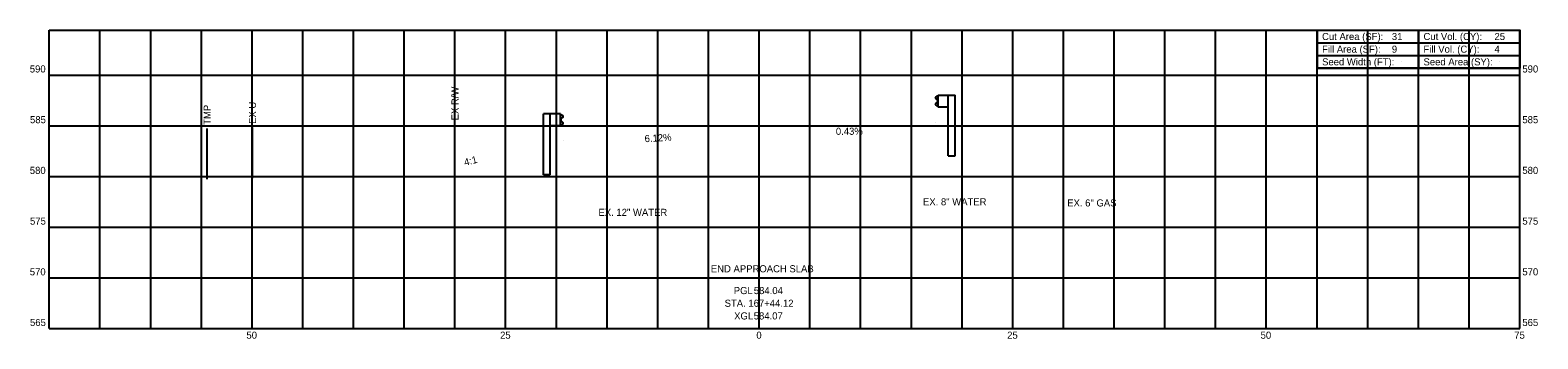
# Model space of a CAD drawing. Extents: x -72 to 77, y 564 to 594.
import ezdxf

# ---------------------------------------------------------------- set-up
doc = ezdxf.new("R2010")
doc.units = 0
for name, color, linetype in [('BD_X_Building', 7, 'Continuous'), ('BD_X_Canopy', 7, 'Continuous'), ('Default', 7, 'Continuous'), ('RD_X_Cells', 7, 'Continuous'), ('RD_X_Concrete_Pad', 7, 'Continuous'), ('RD_X_Fence', 7, 'Continuous'), ('SN_X_Public', 7, 'Continuous'), ('SV_X_Top_of_Bank', 7, 'Continuous'), ('UT_X_Cable_TV', 7, 'Continuous'), ('UT_X_Telecom', 7, 'Continuous')]:
    doc.layers.add(name, color=color, linetype=linetype)

msp = doc.modelspace()

# ---------------------------------------------------------------- linework, layer by layer
at = {"layer": 'BD_X_Canopy'}
msp.add_line((-30, 580.18), (-30, 585.18), dxfattribs=at)
at = {"layer": 'Default'}
msp.add_circle((75, 594.42), 0.000417, dxfattribs=at)
msp.add_circle((75, 594.42), 0.000417, dxfattribs=at)
msp.add_circle((75, 594.42), 0.000417, dxfattribs=at)
msp.add_circle((75, 594.42), 0.000417, dxfattribs=at)
msp.add_circle((75, 594.42), 0.000417, dxfattribs=at)
msp.add_circle((75, 594.42), 0.000417, dxfattribs=at)
msp.add_circle((75, 594.42), 0.000417, dxfattribs=at)
msp.add_circle((75, 594.42), 0.000417, dxfattribs=at)
msp.add_circle((75, 594.42), 0.000417, dxfattribs=at)
msp.add_circle((75, 594.42), 0.000417, dxfattribs=at)
msp.add_circle((75, 594.42), 0.000417, dxfattribs=at)
msp.add_circle((75, 594.42), 0.000417, dxfattribs=at)
at = {"layer": 'RD_X_Concrete_Pad'}
for p, q in [((-70, 594.42), (75, 594.42)), ((-70, 565), (-70, 594.42)), ((-65, 565), (-65, 594.42)), ((-60, 565), (-60, 594.42)), ((-55, 565), (-55, 594.42)), ((-50, 565), (-50, 594.42)), ((-45, 565), (-45, 594.42)), ((-40, 565), (-40, 594.42)), ((-35, 565), (-35, 594.42)), ((-30, 565), (-30, 594.42)), ((-25, 565), (-25, 594.42)), ((-20, 565), (-20, 594.42)), ((-15, 565), (-15, 594.42)), ((-10, 565), (-10, 594.42)), ((-5, 565), (-5, 594.42)), ((0, 565), (0, 594.42)), ((5, 565), (5, 594.42)), ((10, 565), (10, 594.42)), ((15, 565), (15, 594.42)), ((20, 565), (20, 594.42)), ((25, 565), (25, 594.42)), ((30, 565), (30, 594.42)), ((35, 565), (35, 594.42)), ((40, 565), (40, 594.42)), ((45, 565), (45, 594.42)), ((50, 565), (50, 594.42)), ((55, 565), (55, 594.42)), ((60, 565), (60, 594.42)), ((65, 565), (65, 594.42)), ((70, 565), (70, 594.42)), ((75, 565), (75, 594.42)), ((-70, 590), (75, 590)), ((-70, 585), (75, 585)), ((-70, 580), (75, 580)), ((-70, 575), (75, 575)), ((-70, 570), (75, 570)), ((-70, 565), (75, 565))]:
    msp.add_line(p, q, dxfattribs=at)
at = {"layer": 'RD_X_Fence'}
msp.add_lwpolyline([(55, 594.42), (75, 594.42), (75, 590.67), (55, 590.67)], close=True, dxfattribs=at)
at = {"layer": 'SN_X_Public'}
for p, q in [((55, 594.42), (75, 594.42)), ((55, 594.42), (55, 591.92)), ((55, 593.17), (75, 593.17)), ((65, 594.42), (65, 590.67)), ((75, 594.42), (75, 591.92)), ((55, 591.92), (75, 591.92)), ((63.3, 591.3), (63.3, 591.3)), ((72.95, 591.3), (72.95, 591.3))]:
    msp.add_line(p, q, dxfattribs=at)
msp.add_lwpolyline([(55, 591.92), (55, 590.67), (75, 590.67), (75, 591.92)], dxfattribs=at)
at = {"layer": 'SV_X_Top_of_Bank'}
for p, q in [((17.36, 587.76), (17.36, 587.76)), ((17.37, 587.76), (17.37, 587.76)), ((17.54, 587.93), (17.4, 587.83)), ((17.4, 587.82), (17.54, 587.92)), ((17.4, 587.83), (17.4, 587.83)), ((17.4, 587.82), (17.4, 587.82)), ((17.4, 587.69), (17.4, 587.69)), ((17.59, 587.55), (17.4, 587.69)), ((17.4, 587.68), (17.4, 587.68)), ((17.4, 587.68), (17.58, 587.55)), ((17.58, 587.33), (17.4, 587.19)), ((17.4, 587.18), (17.59, 587.32)), ((17.52, 587.92), (17.52, 587.92)), ((17.52, 587.91), (17.52, 587.91)), ((17.52, 587.6), (17.52, 587.6)), ((17.52, 587.6), (17.52, 587.6)), ((17.63, 587.95), (17.54, 587.93)), ((17.54, 587.92), (17.63, 587.94)), ((17.54, 587.93), (17.54, 587.93)), ((17.54, 587.92), (17.54, 587.92)), ((17.58, 587.55), (17.58, 587.55)), ((17.58, 587.33), (17.58, 587.33)), ((17.59, 587.55), (17.59, 587.55)), ((17.59, 587.32), (17.59, 587.32)), ((17.62, 587.48), (17.62, 587.48)), ((17.62, 587.48), (17.62, 587.39)), ((17.62, 587.41), (17.62, 587.47)), ((17.62, 587.39), (17.62, 587.39)), ((17.63, 587.95), (17.63, 587.95)), ((17.63, 587.94), (17.63, 587.95)), ((17.63, 587.94), (17.63, 587.94)), ((17.63, 587.48), (17.63, 587.48)), ((17.63, 587.39), (17.63, 587.48)), ((17.63, 587.41), (17.63, 587.47)), ((17.63, 587.39), (17.63, 587.39)), ((17.64, 588.02), (18.64, 588.02)), ((17.64, 586.85), (17.64, 588.02)), ((18.64, 588.02), (19.31, 588.02)), ((18.64, 582.02), (18.64, 588.02)), ((19.31, 582.02), (19.31, 588.02)), ((-20.6, 586.16), (-21.27, 586.16)), ((-21.27, 580.16), (-21.27, 586.16)), ((-19.6, 586.16), (-20.6, 586.16)), ((-20.6, 580.16), (-20.6, 586.16)), ((-19.6, 584.99), (-19.6, 586.16)), ((-19.59, 586.09), (-19.59, 586.09)), ((-19.59, 586.09), (-19.5, 586.08)), ((-19.59, 586.08), (-19.59, 586.09)), ((-19.59, 586.08), (-19.59, 586.08)), ((-19.5, 586.07), (-19.59, 586.08)), ((-19.55, 585.7), (-19.36, 585.83)), ((-19.36, 585.83), (-19.54, 585.69)), ((-19.5, 586.08), (-19.5, 586.08)), ((-19.5, 586.08), (-19.36, 585.97)), ((-19.5, 586.07), (-19.5, 586.07)), ((-19.36, 585.96), (-19.5, 586.07)), ((-19.48, 586.06), (-19.48, 586.06)), ((-19.48, 586.05), (-19.48, 586.05)), ((-19.48, 585.75), (-19.48, 585.75)), ((-19.48, 585.74), (-19.48, 585.74)), ((-19.36, 585.97), (-19.36, 585.97)), ((-19.36, 585.96), (-19.36, 585.96)), ((-19.36, 585.83), (-19.36, 585.83)), ((-19.36, 585.83), (-19.36, 585.83)), ((-19.33, 585.9), (-19.33, 585.9)), ((-19.32, 585.9), (-19.32, 585.9)), ((17.36, 587.12), (17.36, 587.12)), ((17.37, 587.12), (17.37, 587.12)), ((17.39, 587.05), (17.39, 587.05)), ((17.39, 587.05), (17.54, 586.94)), ((17.4, 587.19), (17.4, 587.19)), ((17.4, 587.18), (17.4, 587.18)), ((17.4, 587.06), (17.4, 587.06)), ((17.54, 586.95), (17.4, 587.06)), ((17.62, 586.93), (17.54, 586.95)), ((17.54, 586.94), (17.62, 586.92)), ((17.62, 586.93), (17.62, 586.93)), ((17.62, 586.92), (17.62, 586.93)), ((17.62, 586.92), (17.62, 586.92)), ((17.64, 586.85), (18.64, 586.85)), ((-19.6, 584.99), (-20.6, 584.99)), ((-19.59, 585.62), (-19.59, 585.62)), ((-19.59, 585.53), (-19.59, 585.62)), ((-19.59, 585.55), (-19.59, 585.61)), ((-19.59, 585.53), (-19.59, 585.53)), ((-19.58, 585.62), (-19.58, 585.62)), ((-19.58, 585.62), (-19.58, 585.53)), ((-19.58, 585.55), (-19.58, 585.61)), ((-19.58, 585.53), (-19.58, 585.53)), ((-19.58, 585.08), (-19.5, 585.09)), ((-19.58, 585.08), (-19.58, 585.08)), ((-19.58, 585.07), (-19.58, 585.08)), ((-19.5, 585.08), (-19.58, 585.07)), ((-19.58, 585.07), (-19.58, 585.07)), ((-19.55, 585.7), (-19.55, 585.7)), ((-19.55, 585.46), (-19.55, 585.46)), ((-19.36, 585.32), (-19.55, 585.46)), ((-19.54, 585.69), (-19.54, 585.69)), ((-19.54, 585.47), (-19.54, 585.47)), ((-19.54, 585.47), (-19.36, 585.33)), ((-19.5, 585.09), (-19.36, 585.2)), ((-19.35, 585.19), (-19.5, 585.08)), ((-19.36, 585.33), (-19.36, 585.33)), ((-19.36, 585.32), (-19.36, 585.32)), ((-19.36, 585.2), (-19.36, 585.2)), ((-19.35, 585.19), (-19.35, 585.19)), ((-19.33, 585.26), (-19.33, 585.26)), ((-19.32, 585.26), (-19.32, 585.26)), ((17.36, 585.35), (17.36, 585.35)), ((-19.32, 583.5), (-19.32, 583.5)), ((18.64, 582.02), (19.31, 582.02)), ((-20.6, 580.16), (-21.27, 580.16))]:
    msp.add_line(p, q, dxfattribs=at)
for points in [[(17.61, 587.46), (17.61, 587.41), (17.58, 587.41), (17.58, 587.46)], [(17.61, 587.5), (17.61, 587.38), (17.62, 587.38), (17.62, 587.5)], [(-19.57, 585.64), (-19.57, 585.52), (-19.58, 585.52), (-19.58, 585.64)], [(-19.57, 585.61), (-19.57, 585.55), (-19.54, 585.55), (-19.54, 585.61)]]:
    msp.add_lwpolyline(points, close=True, dxfattribs=at)
for centre, radius, start, end in [((17.45, 587.76), 0.0886, 126.7788, 233.682), ((17.45, 587.76), 0.0787, 126.7788, 233.682), ((17.54, 587.48), 0.0788, 359.9056, 53.682), ((17.54, 587.39), 0.0788, 306.1293, 359.9056), ((17.54, 587.48), 0.0886, 359.9056, 53.682), ((17.54, 587.39), 0.0886, 306.1293, 359.9056), ((-19.41, 585.9), 0.0886, 306.318, 53.2212), ((-19.41, 585.9), 0.0787, 306.318, 53.2212), ((17.45, 587.12), 0.0886, 126.1293, 233.0325), ((17.45, 587.12), 0.0787, 126.1293, 233.0325), ((-19.5, 585.62), 0.0886, 126.318, 180.0944), ((-19.5, 585.53), 0.0886, 180.0944, 233.8707), ((-19.5, 585.62), 0.0788, 126.318, 180.0944), ((-19.5, 585.53), 0.0788, 180.0944, 233.8707), ((-19.41, 585.26), 0.0886, 306.9675, 53.8707), ((-19.41, 585.26), 0.0787, 306.9675, 53.8707)]:
    msp.add_arc(centre, radius, start, end, dxfattribs=at)
at = {"layer": 'UT_X_Cable_TV'}
msp.add_line((-54.43, 579.74), (-54.43, 584.74), dxfattribs=at)
at = {"layer": 'UT_X_Telecom'}
msp.add_line((-49.97, 579.83), (-49.97, 584.83), dxfattribs=at)

# ---------------------------------------------------------------- texts
at = {"layer": 'BD_X_Building'}
for s, p in [('Cut Area (SF):', (55.5, 593.45)), ('31', (62.38, 593.45)), ('Cut Vol. (CY):', (65.5, 593.45)), ('25', (72.5, 593.45)), ('Seed Width (FT):', (55.5, 590.95)), ('Fill Area (SF):', (55.5, 592.2)), ('9', (62.38, 592.2)), ('Seed Area (SY):', (65.5, 590.95)), ('Fill Vol. (CY):', (65.5, 592.2)), ('4', (72.5, 592.2)), ('590', (-71.92, 590.25)), ('590', (75.25, 590.25)), ('585', (-71.9, 585.25)), ('585', (75.25, 585.25)), ('580', (-71.92, 580.25)), ('580', (75.25, 580.25)), ('575', (-71.9, 575.25)), ('575', (75.25, 575.25)), ('570', (-71.92, 570.25)), ('END APPROACH SLAB', (-4.77, 570.55)), ('570', (75.25, 570.25)), ('PGL ', (-2.51, 568.4)), ('584.04', (-0.53, 568.4)), ('STA. 167+44.12', (-3.41, 567.15)), ('XGL ', (-2.47, 565.9)), ('584.07', (-0.54, 565.9)), ('565', (-71.9, 565.25)), ('565', (75.25, 565.25)), ('50', (-50.56, 564)), ('25', (-25.55, 564)), ('0', (-0.28, 564)), ('25', (24.45, 564)), ('50', (49.44, 564)), ('75', (74.45, 564))]:
    msp.add_text(s, height=0.7, dxfattribs=at).set_placement(p)
for s, rotation, p in [('0.43%', 0.2464, (7.56, 584.1)), ('6.12%', 3.5005, (-11.28, 583.37)), ('4:1', 14.0362, (-29.01, 581.04))]:
    msp.add_text(s, height=0.7, rotation=rotation, dxfattribs=at).set_placement(p)
at = {"layer": 'BD_X_Canopy'}
msp.add_text('EX R/W', height=0.7, rotation=90, dxfattribs=at).set_placement((-29.65, 585.53))
at = {"layer": 'RD_X_Cells'}
for s, p in [('EX. 12" WATER', (-15.85, 576.11)), ('EX. 8" WATER', (16.15, 577.15)), ('EX. 6" GAS', (30.37, 577.04))]:
    msp.add_text(s, height=0.7, dxfattribs=at).set_placement(p)
at = {"layer": 'UT_X_Cable_TV'}
msp.add_text('TMP', height=0.7, rotation=90, dxfattribs=at).set_placement((-54.08, 585.09))
at = {"layer": 'UT_X_Telecom'}
msp.add_text('EX U', height=0.7, rotation=90, dxfattribs=at).set_placement((-49.62, 585.18))

doc.saveas('drawing.dxf')
